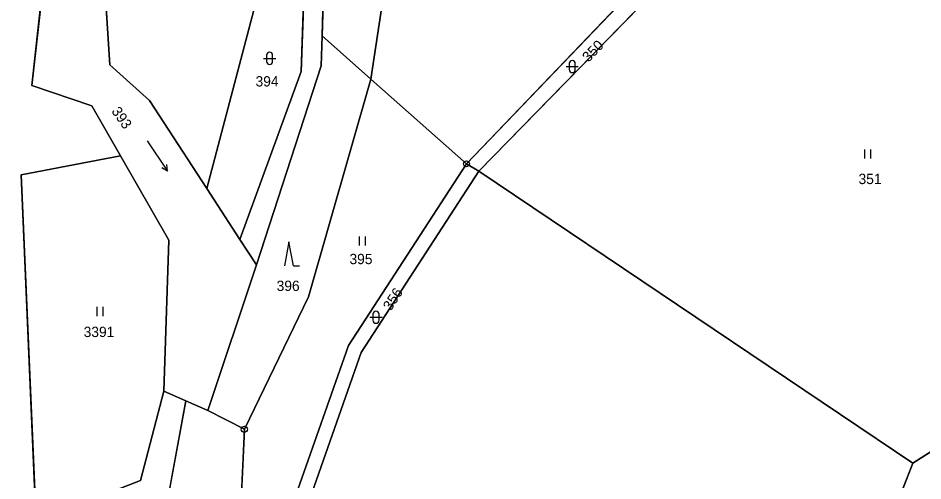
# Model space of a CAD drawing. Extents: x -689422 to -685210, y -987725 to -982160.
# Drawn here: x -686764.7 to -686615.4, y -987141.1 to -987064.7 of the extents above; entities that cross this region are included whole.
import ezdxf

# ---------------------------------------------------------------- set-up
doc = ezdxf.new("R2010")
doc.units = 0
for name, color, linetype in [('KN_Hranice obce', 7, 'Continuous'), ('KN_Hranice_katastrální území', 7, 'Continuous'), ('KN_Hranice_parcel', 7, 'Continuous'), ('KN_Parcelni cisla', 7, 'Continuous'), ('KN_Polygon parcely', 7, 'Continuous'), ('KN_POZEMKY_LESNI POZEMEK', 7, 'Continuous'), ('KN_POZEMKY_OSTATNI PLOCHA', 7, 'Continuous'), ('KN_POZEMKY_TTP', 7, 'Continuous'), ('KN_POZEMKY_VODNI_PLOCHA', 7, 'Continuous'), ('KN_VYUZITI_07_vodni plocha_tok prirozeny', 7, 'Continuous'), ('KN_VYUZITI_17_ostatni plocha_ostatni komunikace', 7, 'Continuous'), ('KN_VYUZITI_27_ostatni plocha_neplodna puda', 7, 'Continuous'), ('KN_Značky bodu BP', 7, 'Continuous'), ('KN_Značky kultur', 7, 'Continuous')]:
    doc.layers.add(name, color=color, linetype=linetype)

msp = doc.modelspace()

# ---------------------------------------------------------------- linework, layer by layer
at = {"layer": 'KN_Hranice obce'}
for points in [[(-686736.98, -987127.84), (-686733.36, -987129.42), (-686727.32, -987132.54), (-686728.62, -987160.8), (-686730.9, -987188.24), (-686726.25, -987220.82), (-686721.3, -987231.04), (-686743.58, -987296.86), (-686755.42, -987332.49), (-686773.36, -987386.48)], [(-686772.91, -987231.1), (-686762.86, -987221.77), (-686759.45, -987206.95), (-686764.56, -987190.07), (-686760.04, -987177.96), (-686762.9, -987155.38), (-686740.07, -987144.66), (-686736.98, -987127.84)]]:
    msp.add_lwpolyline(points, dxfattribs=at)
at = {"layer": 'KN_Hranice_katastrální území'}
for points in [[(-686772.91, -987231.1), (-686762.86, -987221.77), (-686759.45, -987206.95), (-686764.56, -987190.07), (-686760.04, -987177.96), (-686762.9, -987155.38), (-686740.07, -987144.66), (-686736.98, -987127.84), (-686740.61, -987126.26), (-686739.79, -987101.35), (-686747.77, -987087.42), (-686752.49, -987079.19), (-686762.4, -987075.87), (-686759.82, -987052.91)], [(-686759.82, -987052.91), (-686762.4, -987075.87), (-686752.49, -987079.19), (-686747.77, -987087.42), (-686739.79, -987101.35), (-686740.61, -987126.26), (-686736.98, -987127.84)], [(-686736.98, -987127.84), (-686733.36, -987129.42), (-686727.32, -987132.54), (-686728.62, -987160.8), (-686730.9, -987188.24), (-686726.25, -987220.82), (-686721.3, -987231.04), (-686743.58, -987296.86), (-686755.42, -987332.49), (-686773.36, -987386.48)]]:
    msp.add_lwpolyline(points, dxfattribs=at)
at = {"layer": 'KN_Hranice_parcel'}
for p, q in [((-686733.52, -987092.86), (-686716.4, -987027.91)), ((-686713.26, -987028.49), (-686714.49, -987067.68)), ((-686690.67, -987088.77), (-686654.13, -987050.63)), ((-686688.62, -987090), (-686652.37, -987052.87)), ((-686714.49, -987067.68), (-686706.43, -987074.82)), ((-686706.43, -987074.82), (-686690.67, -987088.77)), ((-686747.77, -987087.42), (-686752.49, -987079.19)), ((-686747.77, -987087.42), (-686752.49, -987079.19)), ((-686739.79, -987101.35), (-686747.77, -987087.42)), ((-686739.79, -987101.35), (-686747.77, -987087.42)), ((-686690.67, -987088.77), (-686688.62, -987090)), ((-686617.02, -987138.1), (-686688.62, -987090)), ((-686728.06, -987101.24), (-686733.52, -987092.86)), ((-686740.61, -987126.26), (-686739.79, -987101.35)), ((-686740.61, -987126.26), (-686739.79, -987101.35)), ((-686728.06, -987101.24), (-686725.33, -987105.43)), ((-686733.36, -987129.42), (-686725.33, -987105.43)), ((-686736.98, -987127.84), (-686740.61, -987126.26)), ((-686736.98, -987127.84), (-686740.61, -987126.26)), ((-686736.98, -987127.84), (-686733.36, -987129.42)), ((-686733.36, -987129.42), (-686727.32, -987132.54))]:
    msp.add_line(p, q, dxfattribs=at)
for points in [[(-686674.7, -987019.58), (-686702.89, -987051.19), (-686706.43, -987074.82)], [(-686752.49, -987079.19), (-686762.4, -987075.87), (-686759.82, -987052.91), (-686772.88, -987046.04), (-686802.9, -987044.34), (-686812.43, -987035.47), (-686814.31, -987020.88)], [(-686752.49, -987079.19), (-686762.4, -987075.87), (-686759.82, -987052.91), (-686772.88, -987046.04), (-686802.9, -987044.34), (-686812.43, -987035.47), (-686814.31, -987020.88)], [(-686733.52, -987092.86), (-686742.98, -987078.33), (-686749.49, -987072.45), (-686751.12, -987047.52), (-686771.09, -987035.39), (-686790.62, -987035.24), (-686804, -987026.63)], [(-686716.4, -987027.91), (-686717.94, -987073.53), (-686728.06, -987101.24)], [(-686725.33, -987105.43), (-686714.65, -987072.62), (-686714.49, -987067.68)], [(-686706.43, -987074.82), (-686716.72, -987110.68), (-686727.32, -987132.54)], [(-686761.68, -987147.64), (-686764.13, -987090.59), (-686747.77, -987087.42)], [(-686690.67, -987088.77), (-686710.15, -987118.75), (-686718.88, -987143.57), (-686723.94, -987194.9), (-686718.54, -987231.64), (-686721.3, -987231.04)], [(-686688.62, -987090), (-686708.06, -987119.88), (-686716.52, -987144.01), (-686722.07, -987194.93), (-686717.07, -987230.12), (-686740.4, -987298.25)], [(-686617.02, -987138.1), (-686603.14, -987129.29), (-686574.05, -987105.43)], [(-686761.68, -987147.64), (-686744.46, -987140.99), (-686740.61, -987126.26)], [(-686762.86, -987221.77), (-686759.45, -987206.95), (-686764.56, -987190.07), (-686760.04, -987177.96), (-686762.9, -987155.38), (-686740.07, -987144.66), (-686736.98, -987127.84)], [(-686727.32, -987132.54), (-686728.62, -987160.8), (-686730.9, -987188.24), (-686726.25, -987220.82), (-686721.3, -987231.04)], [(-686663.2, -987255.68), (-686643.34, -987202.52), (-686630.07, -987171.36), (-686617.02, -987138.1)]]:
    msp.add_lwpolyline(points, dxfattribs=at)
at = {"layer": 'KN_Polygon parcely'}
for points in [[(-686747.77, -987087.42), (-686739.79, -987101.35), (-686740.61, -987126.26), (-686736.98, -987127.84), (-686733.36, -987129.42), (-686725.33, -987105.43), (-686728.06, -987101.24), (-686733.52, -987092.86), (-686742.98, -987078.33), (-686749.49, -987072.45), (-686751.12, -987047.52), (-686771.09, -987035.39), (-686790.62, -987035.24), (-686804, -987026.63), (-686807.14, -987011.89), (-686813.46, -987010.33), (-686815.59, -987010.97), (-686814.31, -987020.88), (-686812.43, -987035.47), (-686802.9, -987044.34), (-686772.88, -987046.04), (-686759.82, -987052.91), (-686762.4, -987075.87), (-686752.49, -987079.19)], [(-686713.26, -987028.49), (-686714.49, -987067.68), (-686706.43, -987074.82), (-686702.89, -987051.19), (-686674.7, -987019.58), (-686681.69, -987011.66)], [(-686702.89, -987051.19), (-686706.43, -987074.82), (-686690.67, -987088.77), (-686654.13, -987050.63), (-686659.49, -987043.8), (-686666.47, -987033.78), (-686674.7, -987019.58)], [(-686747.77, -987087.42), (-686752.49, -987079.19), (-686762.4, -987075.87), (-686759.82, -987052.91), (-686772.88, -987046.04), (-686802.9, -987044.34), (-686812.43, -987035.47), (-686814.31, -987020.88), (-686821.44, -987025.8), (-686832.07, -987023.08), (-686833.48, -987027.69), (-686831.23, -987029.88), (-686831.93, -987033.05), (-686832.82, -987035.14), (-686845.63, -987090.8), (-686853.73, -987136.42), (-686847.14, -987139.28), (-686837.96, -987147.68), (-686797.85, -987163.81), (-686768.48, -987167.74), (-686769.48, -987159.76), (-686764.42, -987149.05), (-686761.68, -987147.64), (-686764.13, -987090.59)], [(-686716.4, -987027.91), (-686733.52, -987092.86), (-686728.06, -987101.24), (-686717.94, -987073.53)], [(-686574.05, -987105.43), (-686575.15, -987097.93), (-686581.68, -987076.21), (-686595.53, -987046.88), (-686614.11, -987046.56), (-686652.37, -987052.87), (-686688.62, -987090), (-686617.02, -987138.1), (-686603.14, -987129.29)], [(-686688.62, -987090), (-686652.37, -987052.87), (-686654.13, -987050.63), (-686690.67, -987088.77)], [(-686733.36, -987129.42), (-686727.32, -987132.54), (-686716.72, -987110.68), (-686706.43, -987074.82), (-686714.49, -987067.68), (-686714.65, -987072.62), (-686725.33, -987105.43)], [(-686716.72, -987110.68), (-686727.32, -987132.54), (-686728.62, -987160.8), (-686730.9, -987188.24), (-686726.25, -987220.82), (-686721.3, -987231.04), (-686718.54, -987231.64), (-686723.94, -987194.9), (-686718.88, -987143.57), (-686710.15, -987118.75), (-686690.67, -987088.77), (-686706.43, -987074.82)], [(-686739.79, -987101.35), (-686747.77, -987087.42), (-686764.13, -987090.59), (-686761.68, -987147.64), (-686744.46, -987140.99), (-686740.61, -987126.26)], [(-686718.88, -987143.57), (-686723.94, -987194.9), (-686718.54, -987231.64), (-686721.3, -987231.04), (-686743.58, -987296.86), (-686740.4, -987298.25), (-686717.07, -987230.12), (-686722.07, -987194.93), (-686716.52, -987144.01), (-686708.06, -987119.88), (-686688.62, -987090), (-686690.67, -987088.77), (-686710.15, -987118.75)], [(-686740.4, -987298.25), (-686681.65, -987309.77), (-686663.2, -987255.68), (-686643.34, -987202.52), (-686630.07, -987171.36), (-686617.02, -987138.1), (-686688.62, -987090), (-686708.06, -987119.88), (-686716.52, -987144.01), (-686722.07, -987194.93), (-686717.07, -987230.12)]]:
    msp.add_lwpolyline(points, close=True, dxfattribs=at)
for points in [[(-686751.12, -987047.52), (-686749.49, -987072.45), (-686742.98, -987078.33), (-686733.52, -987092.86), (-686716.4, -987027.91)], [(-686716.4, -987027.91), (-686717.94, -987073.53), (-686728.06, -987101.24), (-686725.33, -987105.43), (-686714.65, -987072.62), (-686714.49, -987067.68), (-686713.26, -987028.49)], [(-686491.96, -987039.41), (-686536.65, -987085.12), (-686574.05, -987105.43), (-686603.14, -987129.29), (-686617.02, -987138.1), (-686630.07, -987171.36), (-686643.34, -987202.52), (-686663.2, -987255.68), (-686681.65, -987309.77), (-686716.15, -987410.94)], [(-686772.91, -987231.1), (-686762.86, -987221.77), (-686759.45, -987206.95), (-686764.56, -987190.07), (-686760.04, -987177.96), (-686762.9, -987155.38), (-686740.07, -987144.66), (-686736.98, -987127.84), (-686740.61, -987126.26), (-686744.46, -987140.99), (-686761.68, -987147.64), (-686764.42, -987149.05), (-686769.48, -987159.76)]]:
    msp.add_lwpolyline(points, dxfattribs=at)
at = {"layer": 'KN_POZEMKY_LESNI POZEMEK'}
for p, q in [((-686714.65, -987072.62), (-686714.49, -987067.68)), ((-686714.49, -987067.68), (-686706.43, -987074.82)), ((-686725.33, -987105.43), (-686714.65, -987072.62)), ((-686706.43, -987074.82), (-686716.72, -987110.68)), ((-686733.36, -987129.42), (-686725.33, -987105.43)), ((-686716.72, -987110.68), (-686727.32, -987132.54)), ((-686727.32, -987132.54), (-686733.36, -987129.42))]:
    msp.add_line(p, q, dxfattribs=at)
at = {"layer": 'KN_POZEMKY_OSTATNI PLOCHA'}
for p, q in [((-686733.52, -987092.86), (-686716.4, -987027.91)), ((-686717.94, -987073.53), (-686716.4, -987027.91)), ((-686716.4, -987027.91), (-686717.94, -987073.53)), ((-686713.26, -987028.49), (-686714.49, -987067.68)), ((-686714.49, -987067.68), (-686713.26, -987028.49)), ((-686702.89, -987051.19), (-686706.43, -987074.82)), ((-686706.43, -987074.82), (-686702.89, -987051.19)), ((-686690.67, -987088.77), (-686654.13, -987050.63)), ((-686654.13, -987050.63), (-686690.67, -987088.77)), ((-686652.37, -987052.87), (-686688.62, -987090)), ((-686714.49, -987067.68), (-686714.65, -987072.62)), ((-686706.43, -987074.82), (-686714.49, -987067.68)), ((-686714.65, -987072.62), (-686725.33, -987105.43)), ((-686728.06, -987101.24), (-686717.94, -987073.53)), ((-686717.94, -987073.53), (-686728.06, -987101.24)), ((-686690.67, -987088.77), (-686706.43, -987074.82)), ((-686710.15, -987118.75), (-686690.67, -987088.77)), ((-686688.62, -987090), (-686690.67, -987088.77)), ((-686690.67, -987088.77), (-686688.62, -987090)), ((-686688.62, -987090), (-686708.06, -987119.88)), ((-686728.06, -987101.24), (-686733.52, -987092.86)), ((-686725.33, -987105.43), (-686728.06, -987101.24)), ((-686718.88, -987143.57), (-686710.15, -987118.75)), ((-686708.06, -987119.88), (-686716.52, -987144.01)), ((-686617.02, -987138.1), (-686603.14, -987129.29)), ((-686630.07, -987171.36), (-686617.02, -987138.1))]:
    msp.add_line(p, q, dxfattribs=at)
at = {"layer": 'KN_POZEMKY_TTP'}
for p, q in [((-686716.4, -987027.91), (-686733.52, -987092.86)), ((-686749.49, -987072.45), (-686751.12, -987047.52)), ((-686759.82, -987052.91), (-686762.4, -987075.87)), ((-686688.62, -987090), (-686652.37, -987052.87)), ((-686742.98, -987078.33), (-686749.49, -987072.45)), ((-686716.72, -987110.68), (-686706.43, -987074.82)), ((-686706.43, -987074.82), (-686690.67, -987088.77)), ((-686762.4, -987075.87), (-686752.49, -987079.19)), ((-686733.52, -987092.86), (-686742.98, -987078.33)), ((-686752.49, -987079.19), (-686747.77, -987087.42)), ((-686747.77, -987087.42), (-686764.13, -987090.59)), ((-686764.13, -987090.59), (-686747.77, -987087.42)), ((-686747.77, -987087.42), (-686739.79, -987101.35)), ((-686690.67, -987088.77), (-686710.15, -987118.75)), ((-686708.06, -987119.88), (-686688.62, -987090)), ((-686617.02, -987138.1), (-686688.62, -987090)), ((-686688.62, -987090), (-686617.02, -987138.1)), ((-686764.13, -987090.59), (-686761.68, -987147.64)), ((-686761.68, -987147.64), (-686764.13, -987090.59)), ((-686739.79, -987101.35), (-686740.61, -987126.26)), ((-686727.32, -987132.54), (-686716.72, -987110.68)), ((-686710.15, -987118.75), (-686718.88, -987143.57)), ((-686716.52, -987144.01), (-686708.06, -987119.88)), ((-686740.61, -987126.26), (-686744.46, -987140.99)), ((-686603.14, -987129.29), (-686617.02, -987138.1)), ((-686728.62, -987160.8), (-686727.32, -987132.54)), ((-686617.02, -987138.1), (-686630.07, -987171.36)), ((-686744.46, -987140.99), (-686761.68, -987147.64))]:
    msp.add_line(p, q, dxfattribs=at)
at = {"layer": 'KN_POZEMKY_VODNI_PLOCHA'}
for p, q in [((-686751.12, -987047.52), (-686749.49, -987072.45)), ((-686762.4, -987075.87), (-686759.82, -987052.91)), ((-686749.49, -987072.45), (-686742.98, -987078.33)), ((-686752.49, -987079.19), (-686762.4, -987075.87)), ((-686742.98, -987078.33), (-686733.52, -987092.86)), ((-686747.77, -987087.42), (-686752.49, -987079.19)), ((-686739.79, -987101.35), (-686747.77, -987087.42)), ((-686733.52, -987092.86), (-686728.06, -987101.24)), ((-686740.61, -987126.26), (-686739.79, -987101.35)), ((-686728.06, -987101.24), (-686725.33, -987105.43)), ((-686725.33, -987105.43), (-686733.36, -987129.42)), ((-686744.46, -987140.99), (-686740.61, -987126.26)), ((-686740.61, -987126.26), (-686736.98, -987127.84)), ((-686736.98, -987127.84), (-686740.61, -987126.26)), ((-686736.98, -987127.84), (-686740.07, -987144.66)), ((-686733.36, -987129.42), (-686736.98, -987127.84)), ((-686761.68, -987147.64), (-686744.46, -987140.99))]:
    msp.add_line(p, q, dxfattribs=at)
at = {"layer": 'KN_VYUZITI_07_vodni plocha_tok prirozeny'}
for p, q in [((-686751.12, -987047.52), (-686749.49, -987072.45)), ((-686762.4, -987075.87), (-686759.82, -987052.91)), ((-686749.49, -987072.45), (-686742.98, -987078.33)), ((-686752.49, -987079.19), (-686762.4, -987075.87)), ((-686742.98, -987078.33), (-686733.52, -987092.86)), ((-686747.77, -987087.42), (-686752.49, -987079.19)), ((-686739.79, -987101.35), (-686747.77, -987087.42)), ((-686733.52, -987092.86), (-686728.06, -987101.24)), ((-686740.61, -987126.26), (-686739.79, -987101.35)), ((-686728.06, -987101.24), (-686725.33, -987105.43)), ((-686725.33, -987105.43), (-686733.36, -987129.42)), ((-686744.46, -987140.99), (-686740.61, -987126.26)), ((-686740.61, -987126.26), (-686736.98, -987127.84)), ((-686736.98, -987127.84), (-686740.61, -987126.26)), ((-686736.98, -987127.84), (-686740.07, -987144.66)), ((-686733.36, -987129.42), (-686736.98, -987127.84)), ((-686761.68, -987147.64), (-686744.46, -987140.99))]:
    msp.add_line(p, q, dxfattribs=at)
at = {"layer": 'KN_VYUZITI_17_ostatni plocha_ostatni komunikace'}
for p, q in [((-686617.02, -987138.1), (-686603.14, -987129.29)), ((-686630.07, -987171.36), (-686617.02, -987138.1))]:
    msp.add_line(p, q, dxfattribs=at)
at = {"layer": 'KN_VYUZITI_27_ostatni plocha_neplodna puda'}
for p, q in [((-686733.52, -987092.86), (-686716.4, -987027.91)), ((-686717.94, -987073.53), (-686716.4, -987027.91)), ((-686716.4, -987027.91), (-686717.94, -987073.53)), ((-686713.26, -987028.49), (-686714.49, -987067.68)), ((-686714.49, -987067.68), (-686713.26, -987028.49)), ((-686702.89, -987051.19), (-686706.43, -987074.82)), ((-686706.43, -987074.82), (-686702.89, -987051.19)), ((-686690.67, -987088.77), (-686654.13, -987050.63)), ((-686654.13, -987050.63), (-686690.67, -987088.77)), ((-686652.37, -987052.87), (-686688.62, -987090)), ((-686714.49, -987067.68), (-686714.65, -987072.62)), ((-686706.43, -987074.82), (-686714.49, -987067.68)), ((-686714.65, -987072.62), (-686725.33, -987105.43)), ((-686728.06, -987101.24), (-686717.94, -987073.53)), ((-686717.94, -987073.53), (-686728.06, -987101.24)), ((-686690.67, -987088.77), (-686706.43, -987074.82)), ((-686710.15, -987118.75), (-686690.67, -987088.77)), ((-686688.62, -987090), (-686690.67, -987088.77)), ((-686690.67, -987088.77), (-686688.62, -987090)), ((-686688.62, -987090), (-686708.06, -987119.88)), ((-686728.06, -987101.24), (-686733.52, -987092.86)), ((-686725.33, -987105.43), (-686728.06, -987101.24)), ((-686718.88, -987143.57), (-686710.15, -987118.75)), ((-686708.06, -987119.88), (-686716.52, -987144.01))]:
    msp.add_line(p, q, dxfattribs=at)
at = {"layer": 'KN_Značky bodu BP'}
for centre, radius in [((-686690.67, -987088.77), 0.5), ((-686690.67, -987088.77), 0.0303), ((-686727.32, -987132.54), 0.5), ((-686727.32, -987132.54), 0.0303)]:
    msp.add_circle(centre, radius, dxfattribs=at)
at = {"layer": 'KN_Značky kultur'}
for p, q in [((-686723.65, -987070.87), (-686723.65, -987071.87)), ((-686722.65, -987071.87), (-686722.65, -987070.87)), ((-686724.15, -987071.37), (-686722.15, -987071.37)), ((-686673.72, -987072.23), (-686673.72, -987073.23)), ((-686672.72, -987073.23), (-686672.72, -987072.23)), ((-686674.22, -987072.73), (-686672.22, -987072.73)), ((-686743.34, -987084.98), (-686739.99, -987089.96)), ((-686624.94, -987087.9), (-686624.94, -987086.4)), ((-686623.94, -987087.9), (-686623.94, -987086.4)), ((-686739.99, -987089.96), (-686740.12, -987088.87)), ((-686739.99, -987089.96), (-686740.95, -987089.43)), ((-686708.34, -987102.26), (-686708.34, -987100.76)), ((-686707.34, -987102.26), (-686707.34, -987100.76)), ((-686719.97, -987101.61), (-686720.72, -987105.61)), ((-686719.22, -987105.61), (-686719.97, -987101.61)), ((-686719.22, -987105.61), (-686718.22, -987105.61)), ((-686751.59, -987113.87), (-686751.59, -987112.37)), ((-686750.59, -987113.87), (-686750.59, -987112.37)), ((-686706.6, -987114.06), (-686704.6, -987114.06)), ((-686706.1, -987113.56), (-686706.1, -987114.56)), ((-686705.1, -987114.56), (-686705.1, -987113.56))]:
    msp.add_line(p, q, dxfattribs=at)
for centre, start, end in [((-686723.15, -987070.87), 0, 180), ((-686723.15, -987071.87), 180, 359.9879), ((-686673.22, -987072.23), 0, 180), ((-686673.22, -987073.23), 180, 359.9879), ((-686705.6, -987113.56), 0, 180), ((-686705.6, -987114.56), 180, 359.9879)]:
    msp.add_arc(centre, 0.5, start, end, dxfattribs=at)

# ---------------------------------------------------------------- texts
at = {"layer": 'KN_Parcelni cisla'}
for s, rotation, p in [('350', 46, (-686670.53, -987072.1)), ('393', 305, (-686749.32, -987080.09)), ('356', 57, (-686703.15, -987113.11))]:
    msp.add_text(s, height=1.7, rotation=rotation, dxfattribs=at).set_placement(p)
for s, p in [('394', (-686725.47, -987076.01)), ('351', (-686625.98, -987092.11)), ('395', (-686709.97, -987105.31)), ('396', (-686721.99, -987109.73)), ('3391', (-686753.83, -987117.33))]:
    msp.add_text(s, height=1.7, dxfattribs=at).set_placement(p)

doc.saveas('drawing.dxf')
